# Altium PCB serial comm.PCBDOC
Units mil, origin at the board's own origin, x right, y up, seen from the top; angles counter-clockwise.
Board outline 6000 x 4000 mil, 2 copper layers (Top Layer, Bottom Layer); 11 components, 19 nets, 50 pads, 0 vias.
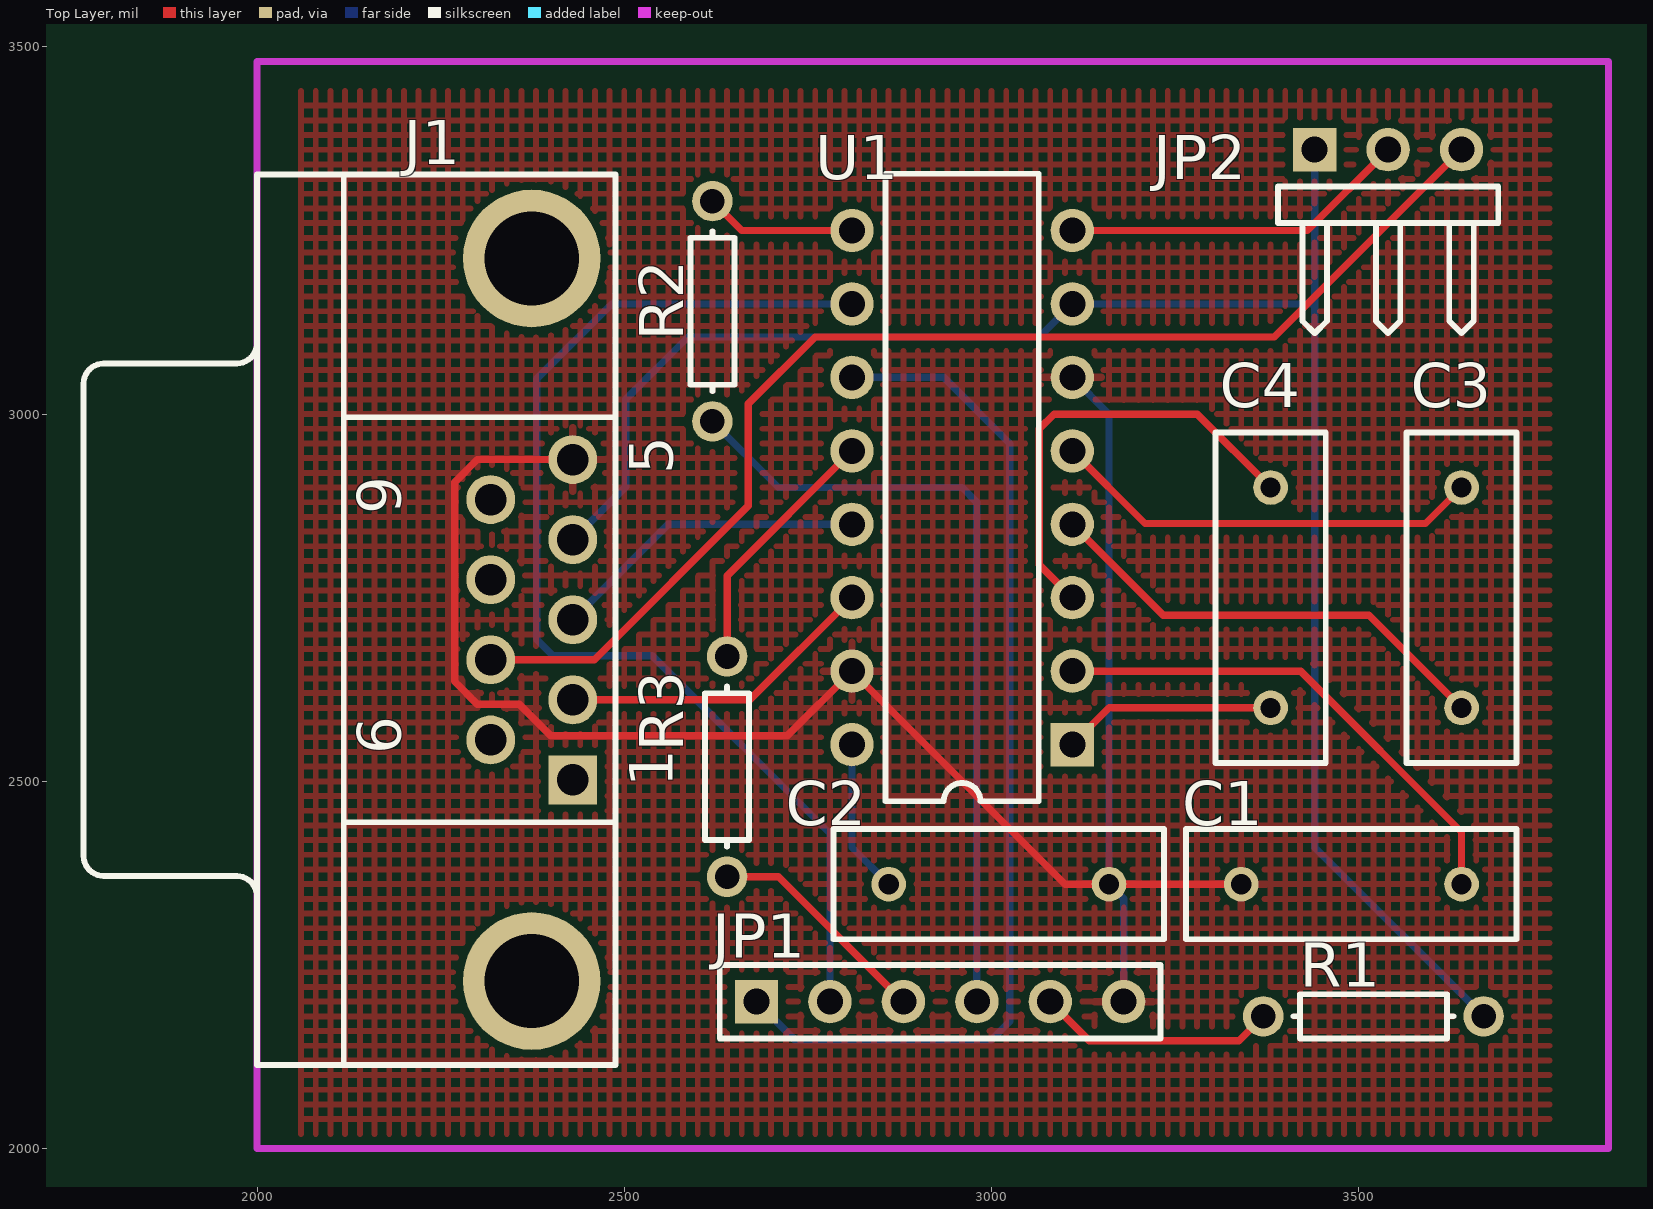
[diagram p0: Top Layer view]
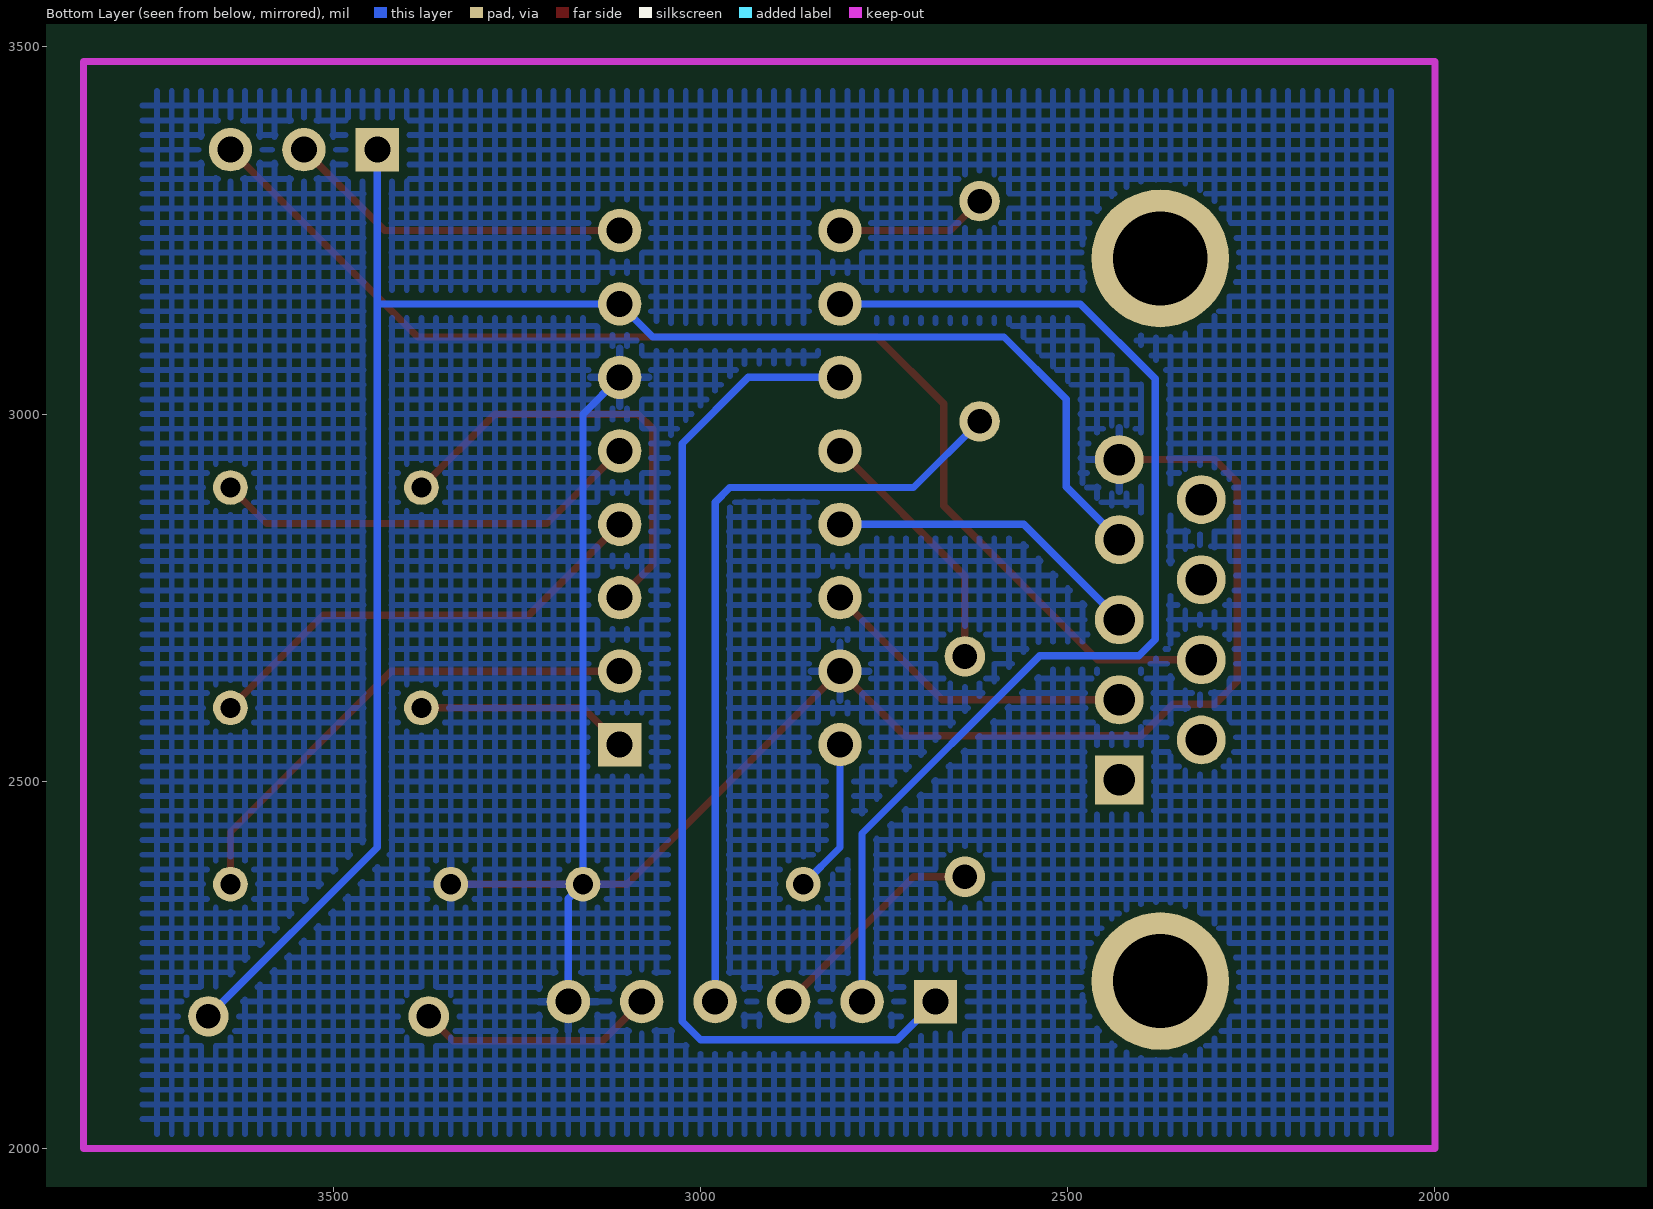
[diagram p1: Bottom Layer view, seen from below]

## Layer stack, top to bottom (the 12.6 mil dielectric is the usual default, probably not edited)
Top Layer: signal copper 1.4
Dielectric: dielectric 12.6, FR-4, Dk 4.8
Bottom Layer: signal copper 1.4

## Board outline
1000,1000 7000,1000 7000,5000 1000,5000

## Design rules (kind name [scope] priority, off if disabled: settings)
Clearance [All] p1: gap=10
ComponentClearance [All] p1: gap=10 collisioncheckmode=0
PolygonConnect [All] p1: connectstyle=Relief reliefconductorwidth=10 reliefentries=4 polygonreliefangle="90 Angle"
RoutingLayers [All] p1: top layer=Horizontal bottom layer=Vertical
RoutingVias [All] p1: holewidth=28 width=50 viastyle="Through Hole" minholewidth=28 minwidth=50 maxholewidth=28 maxwidth=50
SolderMaskExpansion [All] p1: expansion=4
TestPointUsage [All] p1: valid=0 allowmultiple=FALSE
Testpoint [All] p1: side=15 testpointundercomponent=TRUE minsize=40 maxsize=100 preferedsize=60 minholesize=0 maxholesize=40 preferedholesize=32 testpointgrid=1 style=1023 order=1234567890
Width [All] p1: maxlimit=10 minlimit=10 preferedwidth=10
16 further rules are at their usual default settings.

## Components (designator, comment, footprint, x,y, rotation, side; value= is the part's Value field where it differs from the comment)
C1 "0.1μF" RAD-0.3 3340,2360 r0 top
C2 "0.1μF" RAD-0.3 3160,2360 r180 top
C3 "0.1μF" RAD-0.3 3640,2900 r270 top
C4 "0.1μF" RAD-0.3 3380,2600 r90 top
J1 "D Connector 9" DSUB1.385-2H9 2000,2720 r90 top
JP1 "Header 6" HDR1X6 2680,2200 r0 top
JP2 "Header 3H" HDR1X3H 3440,3360 r0 top
R1 "4.7K" AXIAL-0.3 3520,2180 r180 top
R2 "1k" AXIAL-0.3 2620,3140 r90 top
R3 "1k" AXIAL-0.3 2640,2520 r90 top
U1 "MAX232AEJE" DIP-16/D21.7 2960,2900 r90 top

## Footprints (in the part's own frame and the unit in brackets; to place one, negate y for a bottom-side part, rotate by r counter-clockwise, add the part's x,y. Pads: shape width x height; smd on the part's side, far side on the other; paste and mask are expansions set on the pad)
AXIAL-0.3 [mm]
  round 1.4 hole 0.85: 1(-3.81,0) 2(3.81,0)
  silkscreen extent -2.77,-0.76 2.77,0.76
DIP-16/D21.7 [mm]
  rect 1.5x1.5 hole 0.9: 1(-8.89,-3.81)
  round 1.5 hole 0.9: 2(-6.35,-3.81) 3(-3.81,-3.81) 4(-1.27,-3.81) 5(1.27,-3.81) 6(3.81,-3.81) 7(6.35,-3.81) 8(8.89,-3.81) 9(8.89,3.81) 10(6.35,3.81) 11(3.81,3.81) 12(1.27,3.81) 13(-1.27,3.81) 14(-3.81,3.81) 15(-6.35,3.81) 16(-8.89,3.81)
  silkscreen extent -10.85,-2.65 10.85,2.65
DSUB1.385-2H9 [mm]
  rect 1.69x1.69 hole 1.09: 1(-5.54,-10.92)
  round 1.69 hole 1.09: 2(-2.77,-10.92) 3(0,-10.92) 4(2.77,-10.92) 5(5.54,-10.92) 6(-4.155,-8.08) 7(-1.385,-8.08) 8(1.385,-8.08) 9(4.155,-8.08)
  round 4.76 hole 3.26: 10(-12.495,-9.5) 11(12.495,-9.5)
  silkscreen extent -15.4,-12.4 15.4,6
HDR1X3H [mm]
  rect 1.5x1.5 hole 0.9: 1(0,0)
  round 1.5 hole 0.9: 2(2.54,0) 3(5.08,0)
  silkscreen extent -1.27,-6.35 6.35,-1.27
HDR1X6 [mm]
  rect 1.5x1.5 hole 0.9: 1(0,0)
  round 1.5 hole 0.9: 2(2.54,0) 3(5.08,0) 4(7.62,0) 5(10.16,0) 6(12.7,0)
  silkscreen extent -1.27,-1.27 13.97,1.27
RAD-0.3 [mm]
  round 1.2 hole 0.7: 1(0,0) 2(7.62,0)
  silkscreen extent -1.91,-1.91 9.53,1.91

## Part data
C1 C2 C3 C4: library part Cap, "Capacitor"
J1: "Receptacle Assembly, 9 Position, Right Angle"
JP1: "Header, 6-Pin"
JP2: "Header, 3-Pin,  Right Angle"
R1 R2 R3: library part Res1, "Resistor"
U1: "+5V Powered, Multi-Channel RS-232 Driver/Receiver"

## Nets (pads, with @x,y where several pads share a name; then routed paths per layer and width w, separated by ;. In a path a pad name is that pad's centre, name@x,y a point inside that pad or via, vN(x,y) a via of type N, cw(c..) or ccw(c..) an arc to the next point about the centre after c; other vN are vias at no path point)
GND: C1.1 C2.1 J1.5 JP1.6 U1.6 U1.15 | length 2582.1
  Top Layer w10: J1.5 2300,2938.11 2269,2907.11 2269,2636 2300,2605 2357,2605 2400,2562 2722,2562 U1.15 3100,2360 C2.1 C1.1
  Bottom Layer w10: U1.6 3160,3000 C2.1 3180,2340 JP1.6
NetC1_2: C1.2 U1.2 | length 691.7
  Top Layer w10: U1.2 3421,2650 3640,2431 C1.2
NetC2_2: C2.2 U1.16 | length 210.7
  Bottom Layer w10: U1.16 2810,2410 C2.2
NetC3_1: C3.1 U1.5 | length 591.3
  Top Layer w10: U1.5 3209,2851 3591,2851 C3.1
NetC3_2: C3.2 U1.4 | length 633.6
  Top Layer w10: U1.4 3234,2726 3514,2726 C3.2
NetC4_1: C4.1 U1.1 | length 290.7
  Top Layer w10: U1.1 3160,2600 C4.1
NetC4_2: C4.2 U1.3 | length 613.3
  Top Layer w10: U1.3 3065,2795 3065,2980 3085,3000 3280,3000 C4.2
NetJ1_7: J1.7 JP2.3 | length 1691
  Top Layer w10: J1.7 2459.47,2665.47 2669,2875 2669,3014 2760,3105 3385,3105 JP2.3
NetJP1_1: JP1.1 U1.11 | length 1416.2
  Bottom Layer w10: JP1.1 2732,2148 3000,2148 3025,2173 3025,2960 2935,3050 U1.11
NetJP1_2: JP1.2 U1.10 | length 1563.6
  Bottom Layer w10: JP1.2 2780,2429 2538,2671 2403,2671 2381,2693 2381,3048 2483,3150 U1.10
NetJP1_3: JP1.3 R3.1 | length 310.4
  Top Layer w10: R3.1 2710,2370 JP1.3
NetJP1_4: JP1.4 R2.1 | length 1085.6
  Bottom Layer w10: R2.1 2710,2900 2960,2900 2980,2880 JP1.4
NetR2_2: R2.2 U1.9 | length 206.6
  Top Layer w10: R2.2 2660,3250 U1.9
NetR3_2: R3.2 U1.12 | length 350.4
  Top Layer w10: R3.2 2640,2780 U1.12
R1IN: J1.3 U1.13 | length 433.9
  Bottom Layer w10: J1.3 2559.92,2850 U1.13
R2IN: JP2.2 U1.8 | length 475.6
  Top Layer w10: U1.8 3430,3250 JP2.2
T1OUT: J1.2 U1.14 | length 437.7
  Top Layer w10: J1.2 2670.94,2610.94 U1.14
T2OUT: J1.4 JP2.1 R1.1 U1.7 | length 2488
  Bottom Layer w10: J1.4 2502,2901.13 2502,3020.13 2586.87,3105 3065,3105 U1.7 3440,3150 ; JP2.1 3440,3150 ; R1.1 3440,2410 3440,3150
VCC: JP1.5 R1.2 | length 325.6
  Top Layer w10: JP1.5 3133,2147 3337,2147 R1.2
pads on no net: J1.1 J1.6 J1.8 J1.9 J1.10 J1.11

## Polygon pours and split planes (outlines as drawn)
GND on Top Layer (hatched 90Degree grid 20 track 8, remove dead copper): 2060,3440 2060,2020 3760,2020 3760,3440
GND on Bottom Layer (hatched 90Degree grid 20 track 8, remove dead copper): 2060,3440 2060,2020 3760,2020 3760,3440

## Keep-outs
Keep-Out Layer:
  lines w10: 2000,2000 2000,3480 3840,3480 3840,2000 2000,2000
